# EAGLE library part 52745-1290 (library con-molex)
FFC/FPC-to-Board 0.50mm (.020") SMT Top Contact Right Angle, ZIF, Style Receptacle 52745 / 52435 Source: http://www.molex.com/product/ffc/52745.html
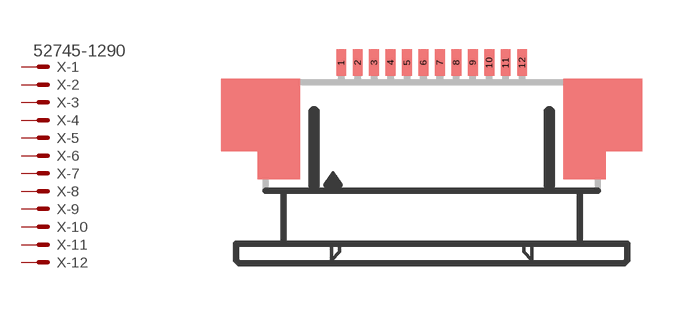
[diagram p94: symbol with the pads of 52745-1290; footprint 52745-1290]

Designator prefix X; gates -1=MV -2=M -3=M -4=M -5=M -6=M -7=M -8=M -9=M -10=M -11=M -12=M

## 52745-1290 (MPN: 52745-1290; OC_FARNELL: unknown; OC_NEWARK: 92M6383)  [52745-1290]
1  -1:S  pas
2  -2:S  pas
3  -3:S  pas
4  -4:S  pas
5  -5:S  pas
6  -6:S  pas
7  -7:S  pas
8  -8:S  pas
9  -9:S  pas
10  -10:S  pas
11  -11:S  pas
12  -12:S  pas

## Footprint 52745-1290 (pad centres in mm)
FFC/FPC-to-Board 0.50mm (.020") SMT Top Contact Right Angle, ZIF, Style Receptacle 52745 / 52435 Source: http://www.molex.com/product/ffc/52745.html
smd 0.3 x 0.8: 1 -2.75,2.5; 2 -2.25,2.5; 3 -1.75,2.5; 4 -1.25,2.5; 5 -0.75,2.5; 6 -0.25,2.5; 7 0.25,2.5; 8 0.75,2.5; 9 1.25,2.5; 10 1.75,2.5; 11 2.25,2.5; 12 2.75,2.5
